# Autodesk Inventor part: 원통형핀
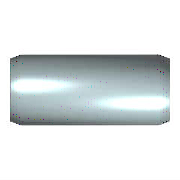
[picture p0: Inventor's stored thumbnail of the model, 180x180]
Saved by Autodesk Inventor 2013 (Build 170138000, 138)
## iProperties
IsCustomPart: 1
Created: 2012-02
Part Number: 원통형핀
Material: 강철, 연강
Description: 평행 핀
Document SubType Name: Modeling
Standard: KS B 1320
Designer: mduedu
Standards Organization: KS
Language: ko-KR
Size Designation: B 2 x  14
Categories: <MemberInstance><Categories><Category DisplayName="조임쇠" InternalName="e4da775c-781d-43d5-af7c-5136215cf5a6" Mnemonic="FSTN"><Category DisplayName="핀" InternalNa
Density: 1 g/cm^3
Author: mduedu
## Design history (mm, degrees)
sketch "스케치"
  geometry: C1 r 1 at (0, 0); 1 further point
  constraints: 1 centre point, 1 coincident
  dimensions: "d1" = 2 diameter of C1 (= NND)
extrude "본체" new body sketch "스케치" distance "d2" = 14 (= NLG); taper "d3" = 0 deg
chamfer "스케치2" distance "d8" = 0.35 (= PHH); stored, may be unused: angle "d9" = 15 deg (= FAWI), second distance "d12" = 0.35 (= PHH)
node "작업 평면1"
node "작업 평면2"
body "Solid1"
chamfer "모따기1" distance "d4" = 0.35 (= PHH); stored, may be unused: angle "d5" = 15 deg (= FAWI), second distance "d11" = 0.35 (= PHH)
other parameters: "NND" = 2 [user parameter; used in 1 equation term], "NLG" = 14 [user parameter; used in 1 equation term], "PHH" = 0.35 [user parameter; used in 4 equation terms], "FAWI" = 15 deg [user parameter; used in 2 equation terms], "d13" = 0, "d15" = 0, "d16" = 0, "KAH" = 0.25 [user parameter]
